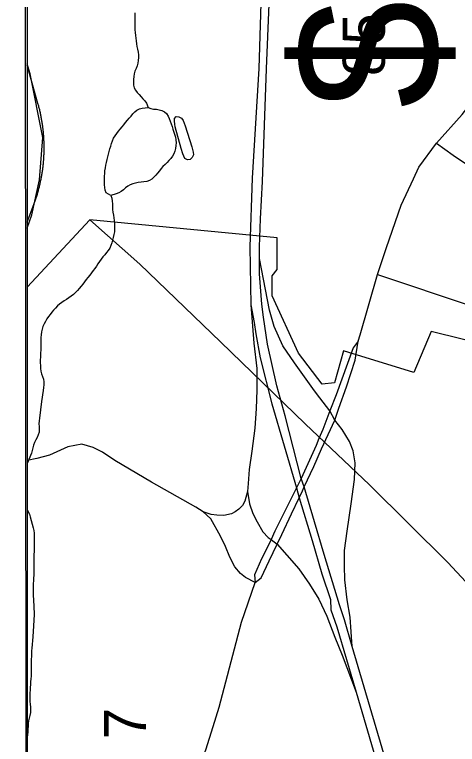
# Model space of a CAD drawing. Extents: x 1373043 to 1375788, y 550128 to 553055.
# Drawn here: x 1373086.2 to 1373167.7, y 550684.8 to 550819 of the extents above; entities that cross this region are included whole.
import ezdxf

# ---------------------------------------------------------------- set-up
doc = ezdxf.new("R2010")
doc.units = 0
for name, color, linetype in [('CTL Sheet Border CELL', 7, 'Continuous'), ('Old_Level_27', 7, 'Continuous'), ('Old_Level_29', 7, 'Continuous'), ('Old_Level_32', 7, 'Continuous'), ('Old_Level_44', 7, 'Continuous'), ('Old_Level_47', 7, 'Continuous'), ('Old_Level_48', 7, 'Continuous'), ('Old_Level_5', 7, 'Continuous'), ('Old_Level_50', 7, 'Continuous'), ('Old_Level_62', 7, 'Continuous'), ('Old_Level_7', 7, 'Continuous'), ('Prop Dimension Text', 7, 'Continuous')]:
    doc.layers.add(name, color=color, linetype=linetype)

msp = doc.modelspace()

# ---------------------------------------------------------------- linework, layer by layer
at = {"layer": 'CTL Sheet Border CELL'}
msp.add_lwpolyline([(1373086.16, 553025.24), (1373088.48, 550416.54), (1374914.56, 550418.17), (1374912.24, 553026.87)], close=True, dxfattribs=at)
at = {"layer": 'Old_Level_27'}
for p, q in [((1373139.47, 550732.2), (1373138.87, 550733.75)), ((1373138.06, 550732.02), (1373138.56, 550730.19))]:
    msp.add_line(p, q, dxfattribs=at)
for points in [[(1373134.28, 550913.04), (1373131.13, 550809.14), (1373129.91, 550788.98), (1373129.44, 550776.33), (1373129.66, 550765.65)], [(1373131.26, 550774.2), (1373131.26, 550776.32), (1373131.43, 550781.46), (1373131.78, 550788.32), (1373132.55, 550809.07), (1373133.03, 550820.97), (1373133.06, 550821.75), (1373133.44, 550832.71)], [(1373138.87, 550733.75), (1373135.96, 550745.23), (1373134.44, 550750.74), (1373132.71, 550758.42), (1373131.96, 550763.39), (1373131.67, 550765.8), (1373131.26, 550771.38), (1373131.26, 550774.2)], [(1373129.66, 550765.65), (1373130.26, 550762.41), (1373130.53, 550760.35), (1373131.37, 550755.89), (1373133.52, 550747.45), (1373138.06, 550732.02)], [(1373148.29, 550702.84), (1373146.86, 550707.72), (1373146.33, 550709.39), (1373145.98, 550710.51), (1373143.14, 550719.74), (1373141.35, 550725.78), (1373139.47, 550732.2)], [(1373138.56, 550730.19), (1373140.94, 550722.32), (1373142.73, 550716.2), (1373144.27, 550711.5), (1373144.37, 550709.57), (1373145.49, 550706.43), (1373149.01, 550694.45)], [(1373166.26, 550641.86), (1373164.86, 550646.6), (1373163.41, 550651.53), (1373148.29, 550702.84)], [(1373149.01, 550694.45), (1373160.92, 550653.84), (1373163.03, 550646.15), (1373164.74, 550641.06)]]:
    msp.add_lwpolyline(points, dxfattribs=at)
at = {"layer": 'Old_Level_29'}
msp.add_line((1373138.87, 550733.75), (1373138.06, 550732.02), dxfattribs=at)
for points in [[(1373163.81, 550795.38), (1373168.55, 550800.66), (1373171.73, 550804.78), (1373174.97, 550811.4), (1373176.39, 550813.21), (1373177.34, 550814.25), (1373179.77, 550815.77), (1373180.53, 550816.15), (1373183.76, 550817.29), (1373187.47, 550818.62), (1373189.9, 550819.53), (1373192.67, 550820.99), (1373193.86, 550822.56), (1373194.91, 550825.65), (1373195.48, 550833.63), (1373195.81, 550837.24), (1373196.6, 550849.12)], [(1373152.92, 550771.23), (1373154.6, 550776.21), (1373157.33, 550783.98), (1373159.57, 550788.85), (1373160.55, 550790.99), (1373163.81, 550795.38)], [(1373149.36, 550759), (1373149.75, 550760.15), (1373152.92, 550771.23)], [(1373149.36, 550759), (1373148.45, 550757.76), (1373145.33, 550749.1), (1373144.2, 550746.16)], [(1373145.08, 550744.44), (1373145.86, 550746.65), (1373147.23, 550750.6), (1373148.84, 550755.46), (1373149.36, 550759)], [(1373144.2, 550746.16), (1373142.89, 550742.73), (1373142.16, 550741.11), (1373141.65, 550739.81), (1373138.87, 550733.75)], [(1373139.47, 550732.2), (1373141.26, 550735.91), (1373142.65, 550739.18), (1373145.08, 550744.44)], [(1373138.06, 550732.02), (1373134.03, 550724.03), (1373133.37, 550722.51)], [(1373138.56, 550730.19), (1373139.14, 550731.46), (1373139.47, 550732.2)], [(1373134.51, 550721.67), (1373135.35, 550723.46), (1373137.11, 550727.21), (1373138.56, 550730.19)], [(1373133.37, 550722.51), (1373132.24, 550720.11), (1373131.63, 550718.93), (1373130.32, 550716.04), (1373130.42, 550714.58)], [(1373130.42, 550714.58), (1373131.56, 550715.48), (1373133.04, 550718.6), (1373134.51, 550721.67)], [(1373088.48, 550635.22), (1373091.27, 550637.56), (1373095.66, 550641.54), (1373097.54, 550644.09), (1373102.54, 550651.92), (1373106.01, 550657.34), (1373108.98, 550661.83), (1373110.92, 550665), (1373116.25, 550672.81), (1373118.87, 550677.64), (1373121.38, 550683.83), (1373122.71, 550688.15), (1373123.79, 550691.65), (1373124.74, 550695.16), (1373127.93, 550707.32), (1373130.42, 550714.58)]]:
    msp.add_lwpolyline(points, dxfattribs=at)
at = {"layer": 'Old_Level_32'}
for points in [[(1373163.81, 550795.38), (1373166.87, 550793.18), (1373171.16, 550790.32), (1373179.36, 550784.35), (1373179.77, 550783.74), (1373180.49, 550781.49), (1373181.33, 550778.11), (1373182.32, 550776.87), (1373186.95, 550773.65), (1373189.1, 550772.08), (1373199.41, 550767.28), (1373203.61, 550765.03), (1373206.88, 550763.91), (1373209.13, 550763.91), (1373212.71, 550764.73), (1373213.75, 550765.3), (1373215.93, 550766.7), (1373218.11, 550768.8), (1373221.47, 550772.83), (1373224.46, 550776.74)], [(1373152.92, 550771.23), (1373170.37, 550765.44), (1373178.65, 550762.89), (1373182.09, 550761.8), (1373188.06, 550759.23), (1373190.35, 550757.26), (1373191.95, 550755.3), (1373192.48, 550753.95), (1373192.97, 550752.85), (1373193.25, 550751.19)], [(1373120.84, 550727.61), (1373119.51, 550728.46), (1373111.33, 550733.06), (1373104.6, 550737.06), (1373102.35, 550738.6), (1373100.61, 550739.42), (1373098.53, 550740.07), (1373095.97, 550739.56), (1373092.61, 550738.01), (1373090.27, 550737.38), (1373088.48, 550737.05)], [(1373130.42, 550714.58), (1373128.66, 550715.5), (1373127.74, 550716.27), (1373126.67, 550717.49), (1373125.75, 550719.28), (1373124.95, 550721.23), (1373124.07, 550723.14), (1373122.27, 550726.29), (1373121.53, 550726.99), (1373120.84, 550727.61)]]:
    msp.add_lwpolyline(points, dxfattribs=at)
at = {"layer": 'Old_Level_44'}
msp.add_line((1373088.48, 550780.84), (1373089.96, 550784.8), dxfattribs=at)
for points in [[(1373090.6, 550802.2), (1373090.46, 550802.69), (1373088.48, 550809.74)], [(1373089.96, 550784.8), (1373090.02, 550784.98), (1373090.08, 550785.14), (1373090.13, 550785.31), (1373090.19, 550785.48), (1373090.24, 550785.65), (1373090.29, 550785.82), (1373090.35, 550785.99), (1373090.4, 550786.16), (1373090.45, 550786.34), (1373090.5, 550786.51), (1373090.54, 550786.68), (1373090.59, 550786.85), (1373090.63, 550787.03), (1373090.68, 550787.2), (1373090.72, 550787.37), (1373090.77, 550787.54), (1373090.81, 550787.72), (1373090.85, 550787.89), (1373090.89, 550788.07), (1373090.93, 550788.24), (1373090.96, 550788.41), (1373091, 550788.59), (1373091.03, 550788.76), (1373091.07, 550788.94), (1373091.1, 550789.11), (1373091.14, 550789.29), (1373091.16, 550789.46), (1373091.2, 550789.64), (1373091.22, 550789.82), (1373091.25, 550789.99), (1373091.28, 550790.17), (1373091.3, 550790.35), (1373091.33, 550790.52), (1373091.35, 550790.7), (1373091.38, 550790.88), (1373091.4, 550791.05), (1373091.42, 550791.23), (1373091.44, 550791.41), (1373091.46, 550791.59), (1373091.47, 550791.76), (1373091.49, 550791.94), (1373091.5, 550792.12), (1373091.52, 550792.29), (1373091.53, 550792.47), (1373091.54, 550792.65), (1373091.55, 550792.83), (1373091.56, 550793.01), (1373091.57, 550793.19), (1373091.58, 550793.37), (1373091.59, 550793.54), (1373091.59, 550793.72), (1373091.6, 550793.9), (1373091.6, 550794.08), (1373091.6, 550794.25), (1373091.6, 550794.43), (1373091.6, 550794.61), (1373091.6, 550794.79), (1373091.6, 550794.97), (1373091.6, 550795.15), (1373091.59, 550795.33), (1373091.59, 550795.5), (1373091.58, 550795.68), (1373091.57, 550795.86), (1373091.57, 550796.04), (1373091.56, 550796.21), (1373091.55, 550796.39), (1373091.53, 550796.57), (1373091.52, 550796.75), (1373091.51, 550796.93), (1373091.49, 550797.11), (1373091.48, 550797.28), (1373091.46, 550797.46), (1373091.44, 550797.64), (1373091.42, 550797.82), (1373091.4, 550798), (1373091.38, 550798.17), (1373091.36, 550798.35), (1373091.34, 550798.52), (1373091.31, 550798.7), (1373091.29, 550798.88), (1373091.26, 550799.06), (1373091.23, 550799.23), (1373091.2, 550799.41), (1373091.17, 550799.58), (1373091.14, 550799.76), (1373091.11, 550799.93), (1373091.08, 550800.11), (1373091.04, 550800.28), (1373091.01, 550800.46), (1373090.97, 550800.63), (1373090.94, 550800.81), (1373090.9, 550800.98), (1373090.86, 550801.16), (1373090.82, 550801.33), (1373090.78, 550801.5), (1373090.73, 550801.68), (1373090.69, 550801.85), (1373090.65, 550802.02), (1373090.6, 550802.2)]]:
    msp.add_lwpolyline(points, dxfattribs=at)
at = {"layer": 'Old_Level_47'}
for p, q in [((1373145.08, 550744.44), (1373144.2, 550746.16)), ((1373133.37, 550722.51), (1373134.51, 550721.67))]:
    msp.add_line(p, q, dxfattribs=at)
for points in [[(1373144.2, 550746.16), (1373142.33, 550748.54), (1373141.37, 550749.82), (1373137.67, 550755), (1373135.54, 550758.12), (1373133.93, 550761.69), (1373133.07, 550764.67), (1373131.26, 550774.2)], [(1373129.66, 550765.65), (1373130.18, 550758.64), (1373130.77, 550753.96), (1373130.74, 550749.95), (1373130.64, 550746.59), (1373130.39, 550742.97), (1373129.82, 550738.78), (1373129.33, 550735.36), (1373129.12, 550732.8), (1373129.05, 550731.31)], [(1373148.29, 550702.84), (1373147.91, 550708.23), (1373147.38, 550711.4), (1373146.94, 550715.08), (1373146.89, 550717.67), (1373146.9, 550720.5), (1373147.38, 550724.04), (1373148.08, 550729.09), (1373148.72, 550733.56), (1373148.84, 550736.59), (1373148.46, 550738.79), (1373147.8, 550740.54), (1373146.44, 550742.74), (1373145.08, 550744.44)], [(1373129.05, 550731.31), (1373128.55, 550729.59), (1373128.1, 550728.75), (1373127.44, 550728.09), (1373126.78, 550727.57), (1373126.05, 550727.24), (1373124.65, 550726.95), (1373123.41, 550726.99), (1373122.34, 550727.1), (1373120.84, 550727.61)], [(1373129.05, 550731.31), (1373129.38, 550729.1), (1373129.98, 550727.29), (1373130.79, 550725.76), (1373131.87, 550723.91), (1373132.84, 550722.86), (1373133.37, 550722.51)], [(1373134.51, 550721.67), (1373136.26, 550719.65), (1373138.49, 550717.09), (1373140.43, 550714.28), (1373142.17, 550711.52), (1373143.61, 550708.4), (1373145.11, 550704.53), (1373146.44, 550701.23), (1373149.01, 550694.45)]]:
    msp.add_lwpolyline(points, dxfattribs=at)
at = {"layer": 'Old_Level_48'}
for points in [[(1373088.48, 550779.75), (1373089.33, 550782.21), (1373090.75, 550788.67), (1373091.33, 550796.44), (1373089.01, 550808.13), (1373088.48, 550809.97)], [(1373199.29, 550746.7), (1373192.67, 550748.68), (1373193.05, 550751.09), (1373187.21, 550750.84), (1373173.36, 550755.66), (1373174.25, 550757.94), (1373162.81, 550760.74), (1373159.64, 550753.25), (1373146.68, 550757.18), (1373145.03, 550751.34), (1373142.74, 550751.09), (1373138.42, 550756.8), (1373133.59, 550767.34), (1373133.59, 550771.02), (1373134.48, 550772.16), (1373134.48, 550778), (1373099.99, 550781.27), (1373088.48, 550768.94)], [(1373236.46, 550697.37), (1373183.99, 550708.12), (1373180.72, 550702.36), (1373165.88, 550718.26), (1373151.49, 550732.55), (1373139.62, 550743.77), (1373124.05, 550758.84), (1373109.22, 550773.14), (1373099.99, 550781.27), (1373088.48, 550768.94)]]:
    msp.add_lwpolyline(points, dxfattribs=at)
at = {"layer": 'Old_Level_50'}
msp.add_line((1373138.16, 550733.07), (1373138.16, 550733.07), dxfattribs=at)
at = {"layer": 'Old_Level_62'}
for points in [[(1373108.3, 550819.34), (1373108.28, 550818.83), (1373108.27, 550818.31), (1373108.26, 550817.79), (1373108.26, 550817.27), (1373108.28, 550816.76), (1373108.31, 550816.24), (1373108.36, 550815.73), (1373108.42, 550815.21), (1373108.48, 550814.7), (1373108.55, 550814.19), (1373108.61, 550813.67), (1373108.68, 550813.16), (1373108.76, 550812.65), (1373108.88, 550812.15), (1373108.99, 550811.64), (1373108.96, 550811.13), (1373108.9, 550810.62), (1373108.82, 550810.1), (1373108.71, 550809.59), (1373108.51, 550809.12), (1373108.32, 550808.65), (1373108.18, 550808.14), (1373108.09, 550807.64), (1373108.05, 550807.12), (1373108.03, 550806.6), (1373108.06, 550806.08), (1373108.19, 550805.59), (1373108.42, 550805.12), (1373108.73, 550804.7), (1373109.07, 550804.31), (1373109.43, 550803.94), (1373109.79, 550803.56), (1373110.13, 550803.18), (1373110.45, 550802.77), (1373110.77, 550801.97)], [(1373103.9, 550785.75), (1373103.44, 550785.99), (1373103.02, 550786.28), (1373102.83, 550786.74), (1373102.68, 550787.75), (1373102.68, 550788.27), (1373102.69, 550788.78), (1373102.71, 550789.3), (1373102.75, 550789.82), (1373102.8, 550790.33), (1373102.87, 550790.85), (1373102.95, 550791.36), (1373103.06, 550791.86), (1373103.18, 550792.36), (1373103.31, 550792.87), (1373103.44, 550793.37), (1373103.57, 550793.87), (1373103.71, 550794.36), (1373103.86, 550794.86), (1373104.01, 550795.36), (1373104.17, 550795.85), (1373104.37, 550796.32), (1373104.65, 550796.76), (1373104.97, 550797.17), (1373105.29, 550797.58), (1373105.61, 550797.98), (1373105.93, 550798.39), (1373106.26, 550798.79), (1373106.59, 550799.2), (1373106.92, 550799.6), (1373107.25, 550799.99), (1373107.59, 550800.38), (1373107.94, 550800.76), (1373108.28, 550801.14), (1373108.67, 550801.47), (1373109.16, 550801.68), (1373109.65, 550801.81), (1373110.17, 550801.89), (1373110.77, 550801.97)], [(1373110.77, 550801.97), (1373111.25, 550801.76), (1373111.75, 550801.67), (1373112.27, 550801.67), (1373112.78, 550801.55), (1373113.27, 550801.39), (1373113.72, 550801.14), (1373114.13, 550800.82), (1373114.41, 550800.38), (1373114.6, 550799.9), (1373114.78, 550799.42), (1373114.96, 550798.93), (1373115.13, 550798.44), (1373115.29, 550797.95), (1373115.75, 550796.49), (1373115.86, 550795.98), (1373115.88, 550795.47), (1373115.83, 550794.95), (1373115.76, 550794.44), (1373115.67, 550793.93), (1373115.48, 550793.45), (1373115.21, 550793.01), (1373114.89, 550792.6), (1373114.56, 550792.2), (1373114.22, 550791.81), (1373113.85, 550791.45), (1373113.47, 550791.1), (1373113.13, 550790.71), (1373112.81, 550790.3), (1373112.49, 550789.9), (1373112.16, 550789.5), (1373111.8, 550789.13), (1373111.4, 550788.8), (1373110.96, 550788.52), (1373110.47, 550788.37), (1373109.96, 550788.29), (1373109.44, 550788.23), (1373108.93, 550788.16), (1373108.42, 550788.05), (1373107.92, 550787.91), (1373107.44, 550787.73), (1373106.99, 550787.48), (1373106.59, 550787.15), (1373106.22, 550786.79), (1373105.79, 550786.49), (1373105.34, 550786.24), (1373104.86, 550786.06), (1373103.9, 550785.75)], [(1373117.11, 550793.44), (1373116.8, 550794.42), (1373115.74, 550798.39), (1373115.64, 550798.9), (1373115.57, 550799.41), (1373115.56, 550799.93), (1373115.91, 550800.28), (1373116.41, 550800.25), (1373116.86, 550799.97), (1373117.16, 550799.56), (1373117.36, 550799.08), (1373117.53, 550798.59), (1373118.75, 550794.7), (1373119.05, 550793.72), (1373119.06, 550793.22), (1373118.82, 550792.76), (1373118.47, 550792.39), (1373117.97, 550792.35), (1373117.49, 550792.57), (1373117.11, 550793.44)], [(1373103.9, 550785.75), (1373104.05, 550785.25), (1373104.14, 550784.74), (1373104.17, 550784.23), (1373104.18, 550783.71), (1373104.2, 550783.19), (1373104.26, 550782.68), (1373104.34, 550782.17), (1373104.42, 550781.66), (1373104.49, 550781.15), (1373104.54, 550780.63), (1373104.57, 550780.12), (1373104.57, 550779.6), (1373104.52, 550779.08), (1373104.44, 550778.57), (1373104.33, 550778.06), (1373104.19, 550777.57), (1373104.04, 550777.07), (1373103.88, 550776.57), (1373103.67, 550776.1), (1373103.4, 550775.66), (1373103.09, 550775.26), (1373102.75, 550774.87), (1373102.4, 550774.48), (1373102.07, 550774.08), (1373101.77, 550773.65), (1373101.49, 550773.22), (1373101.21, 550772.79), (1373100.91, 550772.36), (1373100.6, 550771.95), (1373100.29, 550771.54), (1373099.98, 550771.12), (1373099.67, 550770.71), (1373099.35, 550770.3), (1373099.03, 550769.9), (1373098.71, 550769.49), (1373098.4, 550769.08), (1373098.07, 550768.68), (1373097.72, 550768.3), (1373097.36, 550767.93), (1373096.99, 550767.57), (1373096.58, 550767.25), (1373096.16, 550766.96), (1373095.73, 550766.67), (1373095.29, 550766.38), (1373094.87, 550766.09), (1373094.45, 550765.79), (1373094.05, 550765.46), (1373093.69, 550765.08), (1373093.35, 550764.7), (1373093.01, 550764.31), (1373092.69, 550763.91), (1373092.38, 550763.49), (1373092.09, 550763.06), (1373091.82, 550762.62), (1373091.59, 550762.16), (1373091.39, 550761.68), (1373091.23, 550761.19), (1373091.11, 550760.69), (1373091.03, 550760.17), (1373090.99, 550759.66), (1373090.98, 550759.14), (1373090.99, 550758.62), (1373091.01, 550758.11), (1373090.95, 550756.04), (1373090.88, 550755.53), (1373090.88, 550755.01), (1373090.9, 550754.49), (1373090.95, 550753.98), (1373091.02, 550753.47), (1373091.13, 550752.96), (1373091.3, 550752.47), (1373091.47, 550751.98), (1373091.56, 550751.48), (1373091.55, 550750.96), (1373091.5, 550750.44), (1373091.42, 550749.93), (1373091.13, 550747.89), (1373090.72, 550744.82), (1373090.66, 550744.31), (1373090.63, 550743.79), (1373090.67, 550743.27), (1373090.7, 550742.74), (1373090.67, 550742.23), (1373090.53, 550741.75), (1373090.3, 550741.28), (1373090.05, 550740.82), (1373089.82, 550740.35), (1373089.65, 550739.86), (1373089.51, 550739.37), (1373089.39, 550738.86), (1373089.27, 550738.36), (1373088.49, 550736.51), (1373088.48, 550736.5)], [(1373088.48, 550728.03), (1373088.68, 550727.62), (1373088.9, 550727.15), (1373089.05, 550726.67), (1373089.58, 550724.67), (1373089.69, 550724.17), (1373089.74, 550723.66), (1373089.75, 550723.14), (1373089.75, 550722.62), (1373089.74, 550722.1), (1373089.7, 550718), (1373089.68, 550715.94), (1373089.64, 550715.43), (1373089.62, 550714.91), (1373089.61, 550714.39), (1373089.6, 550713.88), (1373089.59, 550713.36), (1373089.6, 550712.84), (1373089.6, 550712.33), (1373089.68, 550710.27), (1373089.77, 550708.72), (1373089.67, 550706.66), (1373089.54, 550704.6), (1373089.35, 550702.54), (1373089.29, 550702.03), (1373089.26, 550701.51), (1373089.25, 550701), (1373089.24, 550700.48), (1373089.24, 550699.96), (1373089.24, 550699.45), (1373089.24, 550698.93), (1373089.24, 550698.41), (1373089.23, 550697.9), (1373089.22, 550697.38), (1373089.17, 550696.87), (1373089.12, 550696.35), (1373089.06, 550695.84), (1373089.03, 550695.32), (1373089.01, 550694.8), (1373088.99, 550694.29), (1373088.98, 550693.77), (1373088.97, 550693.25), (1373088.99, 550692.74), (1373089.03, 550692.22), (1373089.08, 550691.7), (1373089.11, 550691.19), (1373089.1, 550690.68), (1373088.98, 550690.17), (1373088.82, 550689.68), (1373088.73, 550689.17), (1373088.68, 550688.65), (1373088.65, 550688.14), (1373088.63, 550687.62), (1373088.6, 550687.1), (1373088.55, 550686.59), (1373088.49, 550686.08), (1373088.48, 550686)]]:
    msp.add_lwpolyline(points, dxfattribs=at)
at = {"layer": 'Prop Dimension Text'}
msp.add_lwpolyline([(1373088.48, 550913.04), (1373088.48, 550416.54), (1373584.98, 550416.54), (1373584.98, 550913.04)], close=True, dxfattribs=at)

# ---------------------------------------------------------------- texts
at = {"layer": 'Old_Level_5'}
for s, height, p in [('$', 26.76, (1373164.62, 550801.8)), ('85', 7.751, (1373154.3, 550807.72))]:
    msp.add_text(s, height=height, rotation=90, dxfattribs=at).set_placement(p)
at = {"layer": 'Old_Level_7'}
msp.add_text('7', height=7.75, rotation=90, dxfattribs=at).set_placement((1373110.36, 550685.77))

doc.saveas('drawing.dxf')
